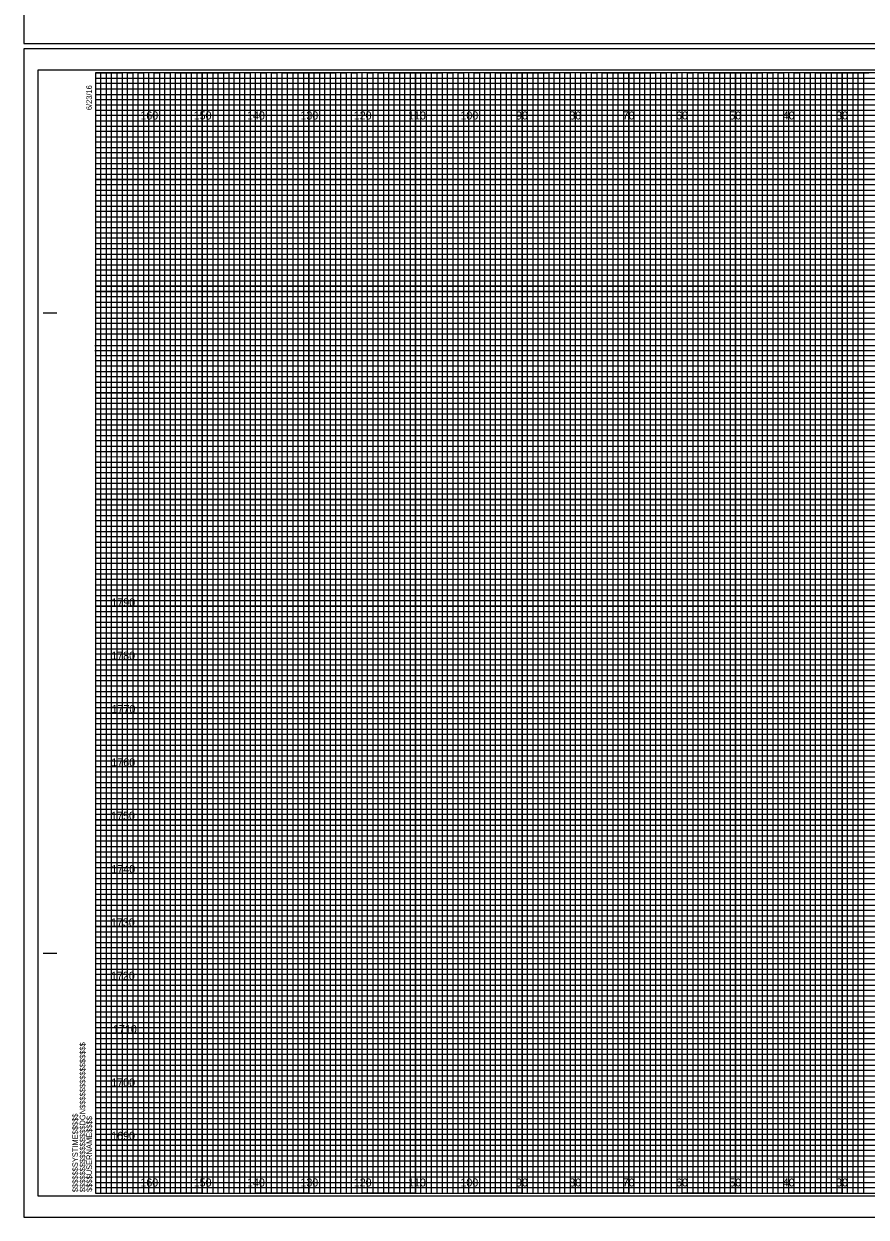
# Model space of a CAD drawing. Extents: x 1443 to 2205, y -29 to 5484.
# Drawn here: x 1867.8 to 2025.7, y 191.1 to 414.7 of the extents above; entities that cross this region are included whole.
import ezdxf

# ---------------------------------------------------------------- set-up
doc = ezdxf.new("R2010")
doc.units = 0
for name, color, linetype in [('Pattern 3', 7, 'Continuous'), ('Prop Retaining Wall', 7, 'Continuous'), ('Prop XS DDE Earthwork Shape', 7, 'Continuous'), ('Prop XS DDE Slope Text', 7, 'Continuous'), ('Prop XS DDE Text', 7, 'Continuous'), ('Prop XS Earthwork Shape', 7, 'Continuous'), ('Prop XS Retaining Wall', 7, 'Continuous'), ('Prop XS Station Labels', 7, 'Continuous'), ('Prop XS Temporary Shoring', 7, 'Continuous'), ('Raster_Level_0', 7, 'Continuous'), ('Scratch_Level_3', 7, 'Continuous')]:
    doc.layers.add(name, color=color, linetype=linetype)

msp = doc.modelspace()

# ---------------------------------------------------------------- linework, layer by layer
at = {"layer": 'Pattern 3'}
for p, q in [((1867.82, 630.05), (1867.82, 411.05)), ((1867.82, 411.05), (2204.52, 411.05)), ((2204.52, 410.05), (1867.82, 410.05)), ((1867.82, 410.05), (1867.82, 191.05)), ((1867.82, 191.05), (2204.52, 191.05))]:
    msp.add_line(p, q, dxfattribs=at)
at = {"layer": 'Prop Retaining Wall'}
for p, q in [((1881.22, 404.55), (2141.22, 404.55)), ((2141.22, 403.53), (1881.22, 403.53)), ((1881.22, 403.53), (1881.22, 402.55)), ((1881.22, 402.55), (2141.22, 402.55)), ((2141.22, 401.44), (1881.22, 401.44)), ((1881.22, 401.44), (1881.22, 399.55)), ((1881.22, 399.55), (2201.22, 399.55))]:
    msp.add_line(p, q, dxfattribs=at)
for points in [[(1881.22, 398.55), (2151.22, 398.55), (2201.22, 398.55), (2201.22, 397.55), (1881.22, 397.55)], [(1881.22, 396.55), (2201.22, 396.55), (2201.22, 394.55), (1881.22, 394.55)], [(1881.22, 393.55), (2201.22, 393.55), (2201.22, 392.55), (1881.22, 392.53)], [(1881.22, 391.55), (2201.22, 391.55), (2201.22, 389.55), (1881.22, 389.55)], [(1881.22, 388.55), (2201.22, 388.55), (2201.22, 387.55), (1881.22, 387.55)], [(1881.22, 386.55), (2201.22, 386.55), (2201.22, 384.55), (1881.22, 384.55)], [(1881.22, 383.55), (2201.22, 383.55), (2201.22, 382.55), (1881.22, 382.55)], [(1881.22, 381.55), (2201.22, 381.55), (2201.22, 379.55), (1881.22, 379.55)], [(1881.22, 378.55), (2201.22, 378.55), (2201.22, 377.55), (1881.22, 377.55)], [(1881.22, 376.55), (2201.22, 376.55), (2201.22, 374.55), (1881.22, 374.55)], [(1881.22, 373.55), (2201.22, 373.55), (2201.22, 372.55), (1881.22, 372.55)], [(1881.22, 371.55), (2201.22, 371.55), (2201.22, 369.5), (2201.22, 368.55), (2201.22, 367.55), (1881.22, 367.55)], [(1881.22, 369.55), (2201.22, 369.55), (2201.22, 368.55), (1881.22, 368.55)], [(1881.22, 366.55), (2201.22, 366.55), (2201.22, 364.55), (1881.22, 364.58)], [(1881.22, 364.58), (2201.22, 364.55), (2201.22, 363.55), (1881.22, 363.55)], [(1881.22, 362.55), (2201.22, 362.55), (2201.22, 361.55), (1881.22, 361.55)], [(1881.22, 359.55), (2201.22, 359.55), (2201.22, 358.55), (1881.22, 358.55)], [(1881.22, 357.55), (2201.22, 357.55), (2201.22, 356.55), (1881.22, 356.55)], [(1881.15, 354.44), (2201.22, 354.44), (2201.22, 353.43), (1881.15, 353.43)], [(1881.22, 352.55), (2201.22, 352.55), (2201.22, 351.55), (1881.22, 351.55)], [(1881.22, 349.55), (2201.22, 349.55), (2201.22, 348.55), (1881.22, 348.55)], [(1881.22, 347.55), (2201.22, 347.55), (2201.22, 346.55), (1881.22, 346.55)], [(1881.22, 344.55), (2201.22, 344.55), (2201.22, 343.55), (1881.22, 343.55)], [(1881.22, 342.55), (2201.22, 342.55), (2201.22, 341.55), (1881.22, 341.55)], [(1881.22, 339.55), (2201.22, 339.55), (2201.22, 338.55), (1881.22, 338.55)], [(1881.22, 337.55), (2201.22, 337.55), (2201.22, 336.55), (1881.22, 336.55)], [(1881.22, 334.55), (2201.22, 334.55), (2201.21, 333.53), (1881.22, 333.55)], [(1881.22, 332.55), (2201.22, 332.55), (2201.22, 331.55), (1881.22, 331.55)], [(1881.22, 329.55), (2201.22, 329.55), (2201.22, 328.55), (1881.22, 328.55)], [(1881.22, 327.55), (2201.22, 327.55), (2201.22, 326.55), (1881.22, 326.55)], [(1881.22, 324.55), (2201.22, 324.55), (2201.22, 323.55), (1881.22, 323.55)], [(1881.22, 322.55), (2201.22, 322.55), (2201.22, 321.55), (1881.22, 321.55)], [(1881.22, 319.55), (2201.22, 319.55), (2201.22, 318.55), (1881.22, 318.55)], [(1881.22, 317.55), (2201.22, 317.55), (2201.22, 316.55), (1881.22, 316.55)], [(1881.22, 314.55), (2201.22, 314.55), (2201.22, 313.55), (1881.22, 313.55)], [(1881.22, 312.54), (2201.29, 312.46), (2201.22, 311.55), (1881.22, 311.55)], [(1881.22, 309.55), (2201.22, 309.55), (2201.22, 308.55), (1881.22, 308.55)], [(1881.22, 307.55), (2201.22, 307.55), (2201.22, 306.55), (1881.22, 306.55)], [(1881.22, 304.55), (2201.22, 304.55), (2201.22, 303.55), (1881.22, 303.55)], [(1881.22, 302.55), (2201.22, 302.55), (2201.22, 301.55), (1881.22, 301.55)], [(1881.22, 299.55), (2201.22, 299.55), (2201.22, 298.55), (1881.22, 298.55)], [(1881.22, 297.55), (2201.22, 297.55), (2201.22, 296.55), (1881.22, 296.55)], [(1881.22, 294.55), (2201.22, 294.55), (2201.22, 293.55), (1881.22, 293.55)], [(1881.22, 292.55), (2201.22, 292.55), (2201.22, 291.55), (1881.22, 291.55)], [(1881.22, 289.55), (2201.22, 289.55), (2201.22, 288.55), (1881.22, 288.55)], [(1881.22, 287.55), (2201.22, 287.55), (2201.22, 286.55), (1881.22, 286.55)], [(1881.22, 284.55), (2201.22, 284.55), (2201.22, 283.55), (1881.22, 283.55)], [(1881.22, 282.55), (2201.22, 282.55), (2201.22, 281.55), (1881.22, 281.55)], [(1881.22, 279.55), (2201.22, 279.55), (2201.22, 278.55), (1881.22, 278.55)], [(1881.22, 277.55), (2201.22, 277.55), (2201.22, 276.55), (1881.22, 276.55)], [(1881.22, 274.55), (2201.22, 274.55), (2201.21, 273.53), (1881.22, 273.55)], [(1881.22, 272.55), (2201.22, 272.55), (2201.22, 271.55), (1881.22, 271.55)], [(1881.22, 269.55), (2201.22, 269.55), (2201.22, 268.55), (1881.22, 268.55)], [(1881.22, 267.55), (2201.22, 267.55), (2201.22, 266.55), (1881.22, 266.55)], [(1881.22, 264.55), (2201.22, 264.55), (2201.22, 263.55), (1881.22, 263.55)], [(1881.22, 262.55), (2201.22, 262.55), (2201.22, 261.55), (1881.22, 261.55)], [(1881.22, 259.55), (2201.22, 259.55), (2201.22, 258.55), (1881.22, 258.55)], [(1881.22, 257.55), (2201.22, 257.55), (2201.22, 256.55), (1881.22, 256.55)], [(1881.22, 254.55), (2201.22, 254.55), (2201.22, 253.55), (1881.22, 253.55)], [(1881.22, 252.54), (2201.29, 252.46), (2201.22, 251.55), (1881.22, 251.55)], [(1881.22, 249.55), (2201.22, 249.55), (2201.22, 248.55), (1881.22, 248.55)], [(1881.22, 247.55), (2201.22, 247.55), (2201.22, 246.55), (1881.22, 246.55)], [(1881.22, 244.55), (2201.22, 244.55), (2201.22, 243.55), (1881.22, 243.55)], [(1881.22, 242.55), (2201.22, 242.55), (2201.22, 241.55), (1881.22, 241.55)], [(1881.22, 239.55), (2201.22, 239.55), (2201.22, 238.55), (1881.22, 238.55)], [(1881.22, 237.55), (2201.22, 237.55), (2201.22, 236.55), (1881.22, 236.55)], [(1881.22, 234.55), (2201.22, 234.55), (2201.22, 233.55), (1881.22, 233.55)], [(1881.22, 232.55), (2201.22, 232.55), (2201.22, 231.55), (1881.22, 231.55)], [(1881.22, 229.55), (2201.22, 229.55), (2201.22, 228.55), (1881.22, 228.55)], [(1881.22, 227.55), (2201.22, 227.55), (2201.22, 226.55), (1881.22, 226.55)], [(1881.22, 224.55), (2201.22, 224.55), (2201.22, 223.55), (1881.22, 223.55)], [(1881.22, 222.55), (2201.22, 222.55), (2201.22, 221.55), (1881.22, 221.55)], [(1881.22, 219.55), (2201.22, 219.55), (2201.22, 218.55), (1881.22, 218.55)], [(1881.22, 217.55), (2201.22, 217.55), (2201.22, 216.55), (1881.22, 216.55)], [(1881.22, 214.55), (2201.22, 214.55), (2201.22, 213.55), (1881.22, 213.55)], [(1881.22, 212.55), (2201.22, 212.55), (2201.22, 211.55), (1881.22, 211.55)], [(1881.22, 209.55), (2201.22, 209.55), (2201.22, 208.55), (1881.22, 208.55)], [(1881.22, 207.55), (2201.22, 207.55), (2201.22, 206.55), (1881.22, 206.55)], [(1881.22, 204.55), (2201.22, 204.55), (2201.22, 203.55), (1881.22, 203.55)], [(1881.22, 202.55), (2201.22, 202.55), (2201.22, 201.55), (1881.22, 201.55)], [(1881.22, 199.55), (2201.22, 199.55), (2201.22, 198.55), (1881.22, 198.55)], [(1881.22, 197.55), (2201.22, 197.55), (2201.22, 196.55), (1881.22, 196.55)]]:
    msp.add_lwpolyline(points, dxfattribs=at)
at = {"layer": 'Prop XS DDE Earthwork Shape'}
msp.add_lwpolyline([(1870.42, 195.05), (2203.62, 195.05), (2203.62, 406.05), (1870.42, 406.05)], close=True, dxfattribs=at)
at = {"layer": 'Prop XS DDE Slope Text'}
for points in [[(1881.22, 195.55), (1882.22, 195.55), (1882.22, 405.55), (1883.22, 405.55), (1883.22, 195.55)], [(1883.22, 195.55), (1884.22, 195.55), (1884.22, 405.55), (1885.22, 405.55), (1885.22, 195.55)], [(1886.22, 195.55), (1887.22, 195.55), (1887.22, 405.55), (1888.22, 405.55), (1888.22, 195.55)], [(1888.22, 195.55), (1889.22, 195.55), (1889.22, 405.55), (1890.22, 405.55), (1890.22, 195.55)], [(1891.22, 195.55), (1892.22, 195.55), (1892.22, 405.55), (1893.22, 405.55), (1893.22, 195.55)], [(1893.22, 195.55), (1894.22, 195.55), (1894.22, 405.55), (1895.22, 405.55), (1895.22, 195.55)], [(1896.22, 195.55), (1897.22, 195.55), (1897.22, 405.55), (1898.22, 405.55), (1898.22, 195.55)], [(1898.22, 195.55), (1899.22, 195.55), (1899.22, 405.55), (1900.22, 405.55), (1900.22, 195.55)], [(1901.22, 195.55), (1902.22, 195.55), (1902.22, 405.55), (1903.22, 405.55), (1903.22, 195.55)], [(1903.22, 195.55), (1904.22, 195.55), (1904.22, 405.55), (1905.22, 405.55), (1905.22, 195.55)], [(1906.22, 195.55), (1907.22, 195.55), (1907.22, 405.55), (1908.22, 405.55), (1908.22, 195.55)], [(1908.22, 195.55), (1909.22, 195.55), (1909.22, 405.55), (1910.22, 405.55), (1910.22, 195.55)], [(1911.22, 195.55), (1912.22, 195.55), (1912.22, 405.55), (1913.22, 405.55), (1913.22, 195.55)], [(1913.22, 195.55), (1914.22, 195.55), (1914.22, 405.55), (1915.22, 405.55), (1915.22, 195.55)], [(1916.22, 195.55), (1917.22, 195.55), (1917.22, 405.55), (1918.22, 405.55), (1918.22, 195.55)], [(1918.22, 195.55), (1919.22, 195.55), (1919.22, 405.55), (1920.22, 405.55), (1920.22, 195.55)], [(1921.22, 195.55), (1922.22, 195.55), (1922.22, 405.55), (1923.22, 405.55), (1923.22, 195.55)], [(1923.22, 195.55), (1924.22, 195.55), (1924.22, 405.55), (1925.22, 405.55), (1925.22, 195.55)], [(1926.22, 195.55), (1927.22, 195.55), (1927.22, 405.55), (1928.22, 405.55), (1928.22, 195.55)], [(1928.22, 195.55), (1929.22, 195.55), (1929.22, 405.55), (1930.22, 405.55), (1930.22, 195.55)], [(1931.22, 195.55), (1932.22, 195.55), (1932.22, 405.55), (1933.22, 405.55), (1933.22, 195.55)], [(1933.22, 195.55), (1934.22, 195.55), (1934.22, 405.55), (1935.22, 405.55), (1935.22, 195.55)], [(1936.22, 195.55), (1937.22, 195.55), (1937.22, 405.55), (1938.22, 405.55), (1938.22, 195.55)], [(1938.22, 195.55), (1939.22, 195.55), (1939.22, 405.55), (1940.22, 405.55), (1940.22, 195.55)], [(1941.22, 195.55), (1942.22, 195.55), (1942.22, 405.55), (1943.22, 405.55), (1943.22, 195.55)], [(1943.22, 195.55), (1944.22, 195.55), (1944.22, 405.55), (1945.22, 405.55), (1945.22, 195.55)], [(1946.22, 195.55), (1947.22, 195.55), (1947.22, 405.55), (1948.22, 405.55), (1948.22, 195.55)], [(1948.22, 195.55), (1949.22, 195.55), (1949.22, 405.55), (1950.22, 405.55), (1950.22, 195.55)], [(1951.22, 195.55), (1952.22, 195.55), (1952.22, 405.55), (1953.22, 405.55), (1953.22, 195.55)], [(1953.22, 195.55), (1954.22, 195.55), (1954.22, 405.55), (1955.22, 405.55), (1955.22, 195.55)], [(1956.22, 195.55), (1957.22, 195.55), (1957.22, 405.55), (1958.22, 405.55), (1958.22, 195.55)], [(1958.22, 195.55), (1959.22, 195.55), (1959.22, 405.55), (1960.22, 405.55), (1960.22, 195.55)], [(1961.22, 195.55), (1962.22, 195.55), (1962.22, 405.55), (1963.22, 405.55), (1963.22, 195.55)], [(1963.22, 195.55), (1964.22, 195.55), (1964.22, 405.55), (1965.22, 405.55), (1965.22, 195.55)], [(1966.22, 195.55), (1967.22, 195.55), (1967.22, 405.55), (1968.22, 405.55), (1968.22, 195.55)], [(1968.22, 195.55), (1969.22, 195.55), (1969.22, 405.55), (1970.22, 405.55), (1970.22, 195.55)], [(1971.22, 195.55), (1972.22, 195.55), (1972.22, 405.55), (1973.22, 405.55), (1973.22, 195.55)], [(1973.22, 195.55), (1974.22, 195.55), (1974.22, 405.55), (1975.22, 405.55), (1975.22, 195.55)], [(1976.22, 195.55), (1977.22, 195.55), (1977.22, 405.55), (1978.22, 405.55), (1978.22, 195.55)], [(1978.22, 195.55), (1979.22, 195.55), (1979.22, 405.55), (1980.22, 405.55), (1980.22, 195.55)], [(1981.22, 195.55), (1982.22, 195.55), (1982.22, 405.55), (1983.22, 405.55), (1983.22, 195.55)], [(1983.22, 195.55), (1984.22, 195.55), (1984.22, 405.55), (1985.22, 405.55), (1985.22, 195.55)], [(1986.22, 195.55), (1987.22, 195.55), (1987.22, 405.55), (1988.22, 405.55), (1988.22, 195.55)], [(1988.22, 195.55), (1989.22, 195.55), (1989.22, 405.55), (1990.22, 405.55), (1990.22, 195.55)], [(1991.22, 195.55), (1992.22, 195.55), (1992.22, 405.55), (1993.22, 405.55), (1993.22, 195.55)], [(1993.22, 195.55), (1994.22, 195.55), (1994.22, 405.55), (1995.22, 405.55), (1995.22, 195.55)], [(1996.22, 195.55), (1997.22, 195.55), (1997.22, 405.55), (1998.22, 405.55), (1998.22, 195.55)], [(1998.22, 195.55), (1999.22, 195.55), (1999.22, 405.55), (2000.22, 405.55), (2000.22, 195.55)], [(2001.22, 195.55), (2002.22, 195.55), (2002.22, 405.55), (2003.22, 405.55), (2003.22, 195.55)], [(2003.22, 195.55), (2004.22, 195.55), (2004.22, 405.55), (2005.22, 405.55), (2005.22, 195.55)], [(2006.22, 195.55), (2007.22, 195.55), (2007.22, 405.55), (2008.22, 405.55), (2008.22, 195.55)], [(2008.22, 195.55), (2009.22, 195.55), (2009.22, 405.55), (2010.22, 405.55), (2010.22, 195.55)], [(2011.22, 195.55), (2012.22, 195.55), (2012.22, 405.55), (2013.22, 405.55), (2013.22, 195.55)], [(2013.22, 195.55), (2014.22, 195.55), (2014.22, 405.55), (2015.22, 405.55), (2015.22, 195.55)], [(2016.22, 195.55), (2017.22, 195.55), (2017.22, 405.55), (2018.22, 405.55), (2018.22, 195.55)], [(2018.22, 195.55), (2019.22, 195.55), (2019.22, 405.55), (2020.22, 405.55), (2020.22, 195.55)], [(2021.22, 195.55), (2022.22, 195.55), (2022.22, 405.55), (2023.22, 405.55), (2023.22, 195.55)], [(2023.22, 195.55), (2024.22, 195.55), (2024.22, 405.55), (2025.22, 405.55), (2025.22, 195.55)]]:
    msp.add_lwpolyline(points, dxfattribs=at)
at = {"layer": 'Prop XS DDE Text'}
for points in [[(1867.82, 411.05), (2204.52, 411.05), (2204.52, 630.05), (1867.82, 630.05)], [(1867.82, 191.05), (2204.52, 191.05), (2204.52, 410.05), (1867.82, 410.05)]]:
    msp.add_lwpolyline(points, close=True, dxfattribs=at)
at = {"layer": 'Prop XS Earthwork Shape'}
for p, q in [((1891.22, 405.55), (1881.22, 405.55)), ((1891.22, 195.55), (1891.22, 405.55)), ((1911.22, 405.55), (1901.22, 405.55)), ((1901.22, 405.55), (1901.22, 195.55)), ((1911.22, 195.55), (1911.22, 405.55)), ((1931.22, 405.55), (1921.22, 405.55)), ((1921.22, 405.55), (1921.22, 195.55)), ((1931.22, 195.55), (1931.22, 405.55)), ((1951.22, 405.55), (1941.22, 405.55)), ((1941.22, 405.55), (1941.22, 195.55)), ((1951.22, 195.55), (1951.22, 405.55)), ((1971.22, 405.55), (1961.22, 405.55)), ((1961.22, 405.55), (1961.22, 195.55)), ((1971.22, 195.55), (1971.22, 405.55)), ((1991.22, 405.55), (1981.22, 405.55)), ((1981.22, 405.55), (1981.22, 195.55)), ((1991.22, 195.55), (1991.22, 405.55)), ((2011.22, 405.55), (2001.22, 405.55)), ((2001.22, 405.55), (2001.22, 195.55)), ((2011.22, 195.55), (2011.22, 405.55)), ((2031.22, 405.55), (2021.22, 405.55)), ((2021.22, 405.55), (2021.22, 195.55)), ((1901.22, 195.55), (1891.22, 195.55)), ((1921.22, 195.55), (1911.22, 195.55)), ((1941.22, 195.55), (1931.22, 195.55)), ((1961.22, 195.55), (1951.22, 195.55)), ((1981.22, 195.55), (1971.22, 195.55)), ((2001.22, 195.55), (1991.22, 195.55)), ((2021.22, 195.55), (2011.22, 195.55))]:
    msp.add_line(p, q, dxfattribs=at)
for points in [[(1881.22, 395.55), (2201.22, 395.55), (2201.22, 385.55), (1881.22, 385.55)], [(1881.22, 375.55), (2201.22, 375.55), (2201.22, 365.55), (1881.22, 365.55)], [(1881.22, 355.55), (2201.22, 355.55), (2201.22, 345.55), (1881.22, 345.55)], [(1881.22, 335.55), (2201.22, 335.55), (2201.22, 325.55), (1881.22, 325.55)], [(1881.22, 315.55), (2201.22, 315.55), (2201.22, 305.55), (1881.22, 305.55)], [(1881.22, 295.55), (2201.22, 295.55), (2201.22, 285.55), (1881.22, 285.55)], [(1881.22, 275.55), (2201.22, 275.55), (2201.22, 265.55), (1881.22, 265.55)], [(1881.22, 255.55), (2201.22, 255.55), (2201.22, 245.55), (1881.22, 245.55)], [(1881.22, 235.55), (2201.22, 235.55), (2201.22, 225.55), (1881.22, 225.55)], [(1881.22, 215.55), (2201.22, 215.55), (2201.22, 205.55), (1881.22, 205.55)]]:
    msp.add_lwpolyline(points, dxfattribs=at)
at = {"layer": 'Prop XS Retaining Wall'}
for p, q in [((1871.42, 360.55), (1873.92, 360.55)), ((1871.52, 360.55), (1874.02, 360.55)), ((1871.42, 240.55), (1873.92, 240.55)), ((1871.52, 240.55), (1874.02, 240.55)), ((1881.22, 195.55), (1881.22, 195.55)), ((1881.22, 195.55), (1881.22, 195.55)), ((1881.22, 195.55), (1881.22, 195.55)), ((1881.22, 195.55), (1881.22, 195.55)), ((1881.22, 195.55), (1881.22, 195.55)), ((1881.22, 195.55), (1881.22, 195.55)), ((1881.22, 195.55), (1881.22, 195.55))]:
    msp.add_line(p, q, dxfattribs=at)
msp.add_lwpolyline([(2201.22, 405.55), (1881.22, 405.55), (1881.22, 195.55), (2201.22, 195.55)], close=True, dxfattribs=at)
at = {"layer": 'Prop XS Station Labels'}
for points in [[(1881.22, 405.55), (1886.22, 405.55), (1886.22, 195.55), (1896.22, 195.55), (1896.22, 405.55), (1906.22, 405.55), (1906.22, 195.55), (1916.22, 195.55), (1916.22, 405.55), (1926.22, 405.55), (1926.22, 195.55), (1936.22, 195.55), (1936.22, 405.55), (1946.22, 405.55), (1946.22, 195.55), (1956.22, 195.55), (1956.22, 405.55), (1966.22, 405.55), (1966.22, 195.55), (1976.22, 195.55), (1976.22, 405.55), (1986.22, 405.55), (1986.22, 195.55), (1996.22, 195.55), (1996.22, 405.55), (2006.22, 405.55), (2006.22, 195.55), (2016.22, 195.55), (2016.22, 405.55), (2026.22, 405.55)], [(1881.22, 400.55), (2156.22, 400.55)], [(1881.22, 380.55), (2201.22, 380.55), (2201.22, 390.55), (1881.22, 390.55)], [(1881.22, 360.55), (2201.22, 360.55), (2201.22, 370.55), (1881.22, 370.55)], [(1881.22, 340.55), (2201.22, 340.55), (2201.22, 350.55), (1881.22, 350.55)], [(1881.22, 320.55), (2201.22, 320.55), (2201.22, 330.55), (1881.22, 330.55)], [(1881.22, 300.55), (2201.22, 300.55), (2201.22, 310.55), (1881.22, 310.55)], [(1881.22, 280.55), (2201.22, 280.55), (2201.22, 290.55), (1881.22, 290.55)], [(1881.22, 260.55), (2201.22, 260.55), (2201.22, 270.55), (1881.22, 270.55)], [(1881.22, 240.55), (2201.22, 240.55), (2201.22, 250.55), (1881.22, 250.55)], [(1881.22, 220.55), (2201.22, 220.55), (2201.22, 230.55), (1881.22, 230.55)], [(1881.22, 200.55), (2201.22, 200.55), (2201.22, 210.55), (1881.22, 210.55)]]:
    msp.add_lwpolyline(points, dxfattribs=at)
at = {"layer": 'Prop XS Temporary Shoring'}
for p, q in [((1891.22, 195.55), (1891.22, 405.55)), ((1901.22, 195.55), (1901.22, 405.55)), ((1911.22, 195.55), (1911.22, 405.55)), ((1921.22, 195.55), (1921.22, 405.55)), ((1931.22, 195.55), (1931.22, 405.55)), ((1941.22, 195.55), (1941.22, 405.55)), ((1951.22, 195.55), (1951.22, 405.55)), ((1961.22, 195.55), (1961.22, 405.55)), ((1971.22, 195.55), (1971.22, 405.55)), ((1981.22, 195.55), (1981.22, 405.55)), ((1991.22, 195.55), (1991.22, 405.55)), ((2001.22, 195.55), (2001.22, 405.55)), ((2011.22, 195.55), (2011.22, 405.55)), ((2021.22, 195.55), (2021.22, 405.55)), ((1881.22, 395.55), (2201.22, 395.55)), ((1881.22, 385.55), (2201.22, 385.55)), ((1881.22, 375.55), (2201.22, 375.55)), ((1881.22, 365.55), (2201.22, 365.55)), ((1881.22, 355.55), (2201.22, 355.55)), ((1881.22, 345.55), (2201.22, 345.55)), ((1881.22, 335.55), (2201.22, 335.55)), ((1881.22, 325.55), (2201.22, 325.55)), ((1881.22, 315.55), (2201.22, 315.55)), ((1881.22, 305.55), (2201.22, 305.55)), ((1881.22, 295.55), (2201.22, 295.55)), ((1881.22, 285.55), (2201.22, 285.55)), ((1881.22, 275.55), (2201.22, 275.55)), ((1881.22, 265.55), (2201.22, 265.55)), ((1881.22, 255.55), (2201.22, 255.55)), ((1881.22, 245.55), (2201.22, 245.55)), ((1881.22, 235.55), (2201.22, 235.55)), ((1881.22, 225.55), (2201.22, 225.55)), ((1881.22, 215.55), (2201.22, 215.55)), ((1881.22, 205.55), (2201.22, 205.55))]:
    msp.add_line(p, q, dxfattribs=at)

# ---------------------------------------------------------------- texts
at = {"layer": 'Prop XS Retaining Wall'}
for s, p in [('6/23/16', (1880.57, 398.55)), ('$$$$$$$$$$$$$$$$DGN$$$$$$$$$$$$$$$$', (1879.34, 195.73)), ('$$$$$$SYSTIME$$$$$', (1877.96, 195.73)), ('$$$$USERNAME$$$$', (1880.6, 195.78))]:
    msp.add_text(s, height=1.05, rotation=90, dxfattribs=at).set_placement(p)
at = {"layer": 'Raster_Level_0'}
for s, p in [('160', (1889.66, 396.8)), ('150', (1899.66, 396.8)), ('140', (1909.66, 396.8)), ('130', (1919.66, 396.8)), ('120', (1929.66, 396.8)), ('110', (1939.84, 396.8)), ('100', (1949.66, 396.8)), ('90', (1960.08, 396.8)), ('80', (1970.08, 396.8)), ('70', (1980.08, 396.8)), ('60', (1990.08, 396.8)), ('50', (2000.08, 396.8)), ('40', (2010.08, 396.8)), ('30', (2020.08, 396.8)), ('160', (1889.66, 196.8)), ('150', (1899.66, 196.8)), ('140', (1909.66, 196.8)), ('130', (1919.66, 196.8)), ('120', (1929.66, 196.8)), ('110', (1939.84, 196.8)), ('100', (1949.66, 196.8)), ('90', (1960.08, 196.8)), ('80', (1970.08, 196.8)), ('70', (1980.08, 196.8)), ('60', (1990.08, 196.8)), ('50', (2000.08, 196.8)), ('40', (2010.08, 196.8)), ('30', (2020.08, 196.8))]:
    msp.add_text(s, height=1.5, dxfattribs=at).set_placement(p)
at = {"layer": 'Scratch_Level_3'}
for s, p in [('1790', (1884.22, 305.55)), ('1780', (1884.2, 295.55)), ('1770', (1884.26, 285.55)), ('1760', (1884.22, 275.55)), ('1750', (1884.18, 265.55)), ('1740', (1884.22, 255.55)), ('1730', (1884.14, 245.55)), ('1720', (1884.15, 235.55)), ('1710', (1884.53, 225.55)), ('1700', (1884.2, 215.55)), ('1690', (1884.19, 205.55))]:
    msp.add_text(s, height=1.5, dxfattribs=at).set_placement(p)

doc.saveas('drawing.dxf')
